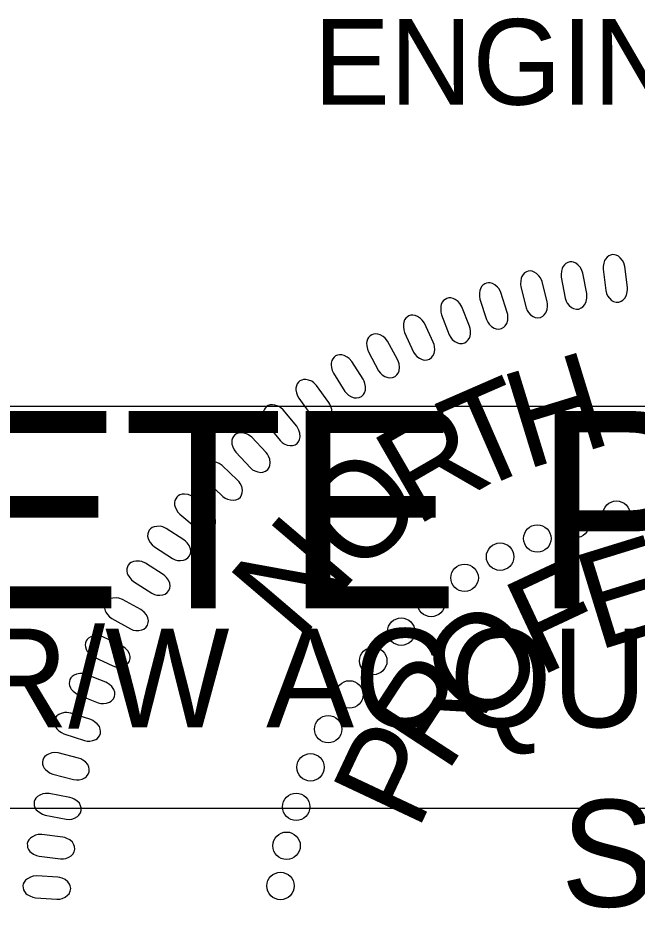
# Model space of a CAD drawing. Extents: x 505602 to 507286, y 483109 to 484209.
# Drawn here: x 507178.9 to 507215, y 484096.7 to 484148.7 of the extents above; entities that cross this region are included whole.
import ezdxf

# ---------------------------------------------------------------- set-up
doc = ezdxf.new("R2010")
doc.units = 0
for name, color, linetype in [('Sheet PE Seal Cell', 7, 'Continuous'), ('Sheet Profile CELL', 7, 'Continuous'), ('Sheet Sticker Incomplete CELL', 7, 'Continuous')]:
    doc.layers.add(name, color=color, linetype=linetype)

msp = doc.modelspace()

# ---------------------------------------------------------------- linework, layer by layer
at = {"layer": 'Sheet PE Seal Cell'}
for points in [[(507214.482, 484132.953), (507214.328, 484134.17), (507214.264, 484134.383), (507214.194, 484134.515), (507214.062, 484134.669), (507213.952, 484134.766), (507213.831, 484134.831), (507213.722, 484134.857), (507213.608, 484134.863), (507213.499, 484134.829), (507213.384, 484134.785), (507213.288, 484134.712), (507213.196, 484134.6), (507213.147, 484134.514), (507213.099, 484134.357), (507213.062, 484134.171), (507213.06, 484134.01), (507213.21, 484132.763), (507213.253, 484132.597), (507213.315, 484132.464), (507213.424, 484132.317), (507213.553, 484132.193), (507213.659, 484132.126), (507213.822, 484132.085), (507213.973, 484132.084), (507214.116, 484132.143), (507214.214, 484132.206), (507214.328, 484132.32), (507214.425, 484132.503), (507214.469, 484132.69), (507214.483, 484132.822)], [(507212.1, 484132.585), (507211.871, 484133.789), (507211.793, 484133.998), (507211.716, 484134.126), (507211.574, 484134.271), (507211.458, 484134.361), (507211.333, 484134.418), (507211.223, 484134.438), (507211.109, 484134.437), (507211.002, 484134.396), (507210.891, 484134.344), (507210.799, 484134.266), (507210.714, 484134.148), (507210.671, 484134.058), (507210.633, 484133.899), (507210.608, 484133.712), (507210.615, 484133.551), (507210.843, 484132.315), (507210.897, 484132.152), (507210.967, 484132.024), (507211.085, 484131.884), (507211.221, 484131.767), (507211.332, 484131.707), (507211.497, 484131.678), (507211.647, 484131.687), (507211.787, 484131.754), (507211.881, 484131.822), (507211.987, 484131.944), (507212.073, 484132.133), (507212.105, 484132.322), (507212.11, 484132.454)], [(507209.795, 484132.113), (507209.491, 484133.301), (507209.4, 484133.504), (507209.314, 484133.627), (507209.164, 484133.763), (507209.042, 484133.845), (507208.914, 484133.894), (507208.802, 484133.908), (507208.689, 484133.899), (507208.585, 484133.852), (507208.477, 484133.793), (507208.39, 484133.709), (507208.314, 484133.586), (507208.276, 484133.494), (507208.247, 484133.332), (507208.234, 484133.144), (507208.252, 484132.984), (507208.557, 484131.764), (507208.621, 484131.606), (507208.699, 484131.482), (507208.826, 484131.349), (507208.969, 484131.242), (507209.083, 484131.189), (507209.25, 484131.169), (507209.4, 484131.188), (507209.535, 484131.263), (507209.624, 484131.337), (507209.722, 484131.466), (507209.795, 484131.66), (507209.816, 484131.851), (507209.813, 484131.983)], [(507207.461, 484131.492), (507207.083, 484132.659), (507206.98, 484132.856), (507206.887, 484132.972), (507206.728, 484133.099), (507206.602, 484133.174), (507206.47, 484133.215), (507206.358, 484133.221), (507206.246, 484133.205), (507206.145, 484133.152), (507206.041, 484133.086), (507205.96, 484132.997), (507205.891, 484132.87), (507205.859, 484132.775), (507205.84, 484132.612), (507205.839, 484132.423), (507205.867, 484132.264), (507206.248, 484131.067), (507206.322, 484130.913), (507206.407, 484130.794), (507206.542, 484130.669), (507206.692, 484130.571), (507206.809, 484130.525), (507206.977, 484130.517), (507207.125, 484130.544), (507207.255, 484130.628), (507207.339, 484130.708), (507207.429, 484130.842), (507207.49, 484131.04), (507207.499, 484131.232), (507207.487, 484131.364)], [(507205.261, 484130.675), (507204.809, 484131.816), (507204.694, 484132.007), (507204.594, 484132.117), (507204.427, 484132.234), (507204.297, 484132.3), (507204.163, 484132.333), (507204.051, 484132.331), (507203.94, 484132.308), (507203.843, 484132.249), (507203.742, 484132.177), (507203.667, 484132.083), (507203.606, 484131.952), (507203.58, 484131.856), (507203.572, 484131.692), (507203.583, 484131.503), (507203.621, 484131.346), (507204.076, 484130.175), (507204.159, 484130.026), (507204.253, 484129.912), (507204.395, 484129.797), (507204.55, 484129.708), (507204.67, 484129.669), (507204.838, 484129.672), (507204.984, 484129.709), (507205.108, 484129.801), (507205.187, 484129.885), (507205.269, 484130.025), (507205.318, 484130.226), (507205.314, 484130.418), (507205.295, 484130.55)], [(507203.143, 484129.743), (507202.621, 484130.853), (507202.494, 484131.035), (507202.387, 484131.14), (507202.214, 484131.246), (507202.079, 484131.303), (507201.944, 484131.328), (507201.832, 484131.319), (507201.722, 484131.29), (507201.629, 484131.224), (507201.534, 484131.146), (507201.464, 484131.048), (507201.412, 484130.913), (507201.392, 484130.815), (507201.395, 484130.651), (507201.417, 484130.463), (507201.464, 484130.309), (507201.993, 484129.169), (507202.085, 484129.025), (507202.185, 484128.918), (507202.334, 484128.812), (507202.495, 484128.733), (507202.617, 484128.702), (507202.784, 484128.715), (507202.928, 484128.76), (507203.046, 484128.86), (507203.12, 484128.95), (507203.192, 484129.094), (507203.229, 484129.298), (507203.213, 484129.489), (507203.185, 484129.619)], [(507201.06, 484128.729), (507200.469, 484129.804), (507200.331, 484129.979), (507200.218, 484130.076), (507200.038, 484130.17), (507199.9, 484130.22), (507199.764, 484130.236), (507199.653, 484130.22), (507199.545, 484130.184), (507199.456, 484130.113), (507199.366, 484130.029), (507199.303, 484129.926), (507199.259, 484129.788), (507199.245, 484129.689), (507199.258, 484129.526), (507199.292, 484129.339), (507199.349, 484129.189), (507199.948, 484128.084), (507200.049, 484127.946), (507200.156, 484127.845), (507200.311, 484127.749), (507200.477, 484127.68), (507200.6, 484127.657), (507200.767, 484127.68), (507200.907, 484127.735), (507201.019, 484127.841), (507201.087, 484127.935), (507201.15, 484128.084), (507201.173, 484128.29), (507201.146, 484128.48), (507201.109, 484128.608)], [(507199.043, 484127.587), (507198.386, 484128.623), (507198.237, 484128.788), (507198.118, 484128.878), (507197.933, 484128.962), (507197.792, 484129.002), (507197.655, 484129.009), (507197.544, 484128.987), (507197.439, 484128.943), (507197.355, 484128.867), (507197.27, 484128.777), (507197.214, 484128.671), (507197.179, 484128.531), (507197.171, 484128.431), (507197.194, 484128.269), (507197.24, 484128.085), (507197.306, 484127.938), (507197.973, 484126.873), (507198.083, 484126.742), (507198.196, 484126.648), (507198.357, 484126.561), (507198.526, 484126.504), (507198.651, 484126.488), (507198.816, 484126.522), (507198.952, 484126.585), (507199.058, 484126.698), (507199.119, 484126.797), (507199.173, 484126.949), (507199.183, 484127.156), (507199.144, 484127.344), (507199.1, 484127.469)], [(507197.042, 484126.232), (507196.321, 484127.225), (507196.162, 484127.38), (507196.038, 484127.463), (507195.847, 484127.534), (507195.704, 484127.566), (507195.567, 484127.564), (507195.458, 484127.535), (507195.356, 484127.485), (507195.277, 484127.404), (507195.198, 484127.309), (507195.149, 484127.199), (507195.122, 484127.057), (507195.121, 484126.957), (507195.155, 484126.796), (507195.211, 484126.616), (507195.287, 484126.474), (507196.019, 484125.453), (507196.137, 484125.329), (507196.255, 484125.242), (507196.421, 484125.165), (507196.594, 484125.118), (507196.72, 484125.111), (507196.882, 484125.155), (507197.015, 484125.227), (507197.112, 484125.347), (507197.167, 484125.448), (507197.212, 484125.604), (507197.209, 484125.811), (507197.158, 484125.996), (507197.106, 484126.119)], [(507195.162, 484124.843), (507194.38, 484125.789), (507194.212, 484125.934), (507194.082, 484126.008), (507193.888, 484126.067), (507193.743, 484126.09), (507193.606, 484126.08), (507193.5, 484126.044), (507193.401, 484125.988), (507193.327, 484125.901), (507193.254, 484125.802), (507193.211, 484125.689), (507193.194, 484125.545), (507193.199, 484125.446), (507193.242, 484125.287), (507193.31, 484125.111), (507193.395, 484124.973), (507194.189, 484124.001), (507194.315, 484123.884), (507194.439, 484123.805), (507194.609, 484123.74), (507194.785, 484123.704), (507194.911, 484123.704), (507195.07, 484123.758), (507195.198, 484123.838), (507195.287, 484123.964), (507195.336, 484124.069), (507195.371, 484124.226), (507195.354, 484124.433), (507195.292, 484124.614), (507195.232, 484124.734)], [(507193.374, 484123.304), (507192.535, 484124.199), (507192.357, 484124.333), (507192.223, 484124.4), (507192.025, 484124.446), (507191.88, 484124.46), (507191.744, 484124.441), (507191.64, 484124.399), (507191.544, 484124.337), (507191.476, 484124.245), (507191.409, 484124.141), (507191.374, 484124.026), (507191.366, 484123.882), (507191.377, 484123.783), (507191.43, 484123.628), (507191.51, 484123.456), (507191.602, 484123.325), (507192.457, 484122.403), (507192.589, 484122.294), (507192.717, 484122.224), (507192.892, 484122.169), (507193.07, 484122.143), (507193.195, 484122.151), (507193.35, 484122.215), (507193.473, 484122.303), (507193.554, 484122.435), (507193.597, 484122.543), (507193.622, 484122.702), (507193.593, 484122.907), (507193.518, 484123.085), (507193.452, 484123.199)], [(507191.712, 484121.695), (507190.818, 484122.535), (507190.632, 484122.658), (507190.495, 484122.715), (507190.294, 484122.75), (507190.148, 484122.754), (507190.013, 484122.727), (507189.912, 484122.678), (507189.821, 484122.61), (507189.759, 484122.515), (507189.699, 484122.407), (507189.67, 484122.29), (507189.671, 484122.145), (507189.689, 484122.047), (507189.751, 484121.895), (507189.841, 484121.729), (507189.942, 484121.603), (507190.853, 484120.737), (507190.992, 484120.638), (507191.124, 484120.575), (507191.302, 484120.531), (507191.48, 484120.517), (507191.605, 484120.533), (507191.757, 484120.606), (507191.873, 484120.702), (507191.946, 484120.838), (507191.982, 484120.948), (507191.996, 484121.11), (507191.955, 484121.313), (507191.87, 484121.485), (507191.796, 484121.595)], [(507190.098, 484119.908), (507189.154, 484120.69), (507188.96, 484120.801), (507188.82, 484120.85), (507188.617, 484120.872), (507188.471, 484120.867), (507188.339, 484120.831), (507188.241, 484120.776), (507188.154, 484120.702), (507188.098, 484120.604), (507188.045, 484120.492), (507188.024, 484120.374), (507188.034, 484120.229), (507188.057, 484120.132), (507188.13, 484119.985), (507188.23, 484119.824), (507188.338, 484119.706), (507189.301, 484118.899), (507189.446, 484118.807), (507189.583, 484118.753), (507189.763, 484118.721), (507189.941, 484118.718), (507190.065, 484118.742), (507190.211, 484118.825), (507190.322, 484118.927), (507190.387, 484119.068), (507190.415, 484119.18), (507190.419, 484119.342), (507190.365, 484119.542), (507190.27, 484119.708), (507190.188, 484119.814)], [(507188.574, 484118.206), (507187.544, 484118.872), (507187.339, 484118.959), (507187.193, 484118.991), (507186.99, 484118.989), (507186.845, 484118.967), (507186.718, 484118.916), (507186.628, 484118.85), (507186.55, 484118.766), (507186.505, 484118.661), (507186.466, 484118.544), (507186.459, 484118.424), (507186.486, 484118.282), (507186.52, 484118.189), (507186.61, 484118.051), (507186.728, 484117.903), (507186.85, 484117.798), (507187.901, 484117.11), (507188.056, 484117.036), (507188.197, 484116.999), (507188.38, 484116.987), (507188.558, 484117.006), (507188.678, 484117.044), (507188.813, 484117.144), (507188.911, 484117.258), (507188.959, 484117.405), (507188.974, 484117.52), (507188.959, 484117.681), (507188.882, 484117.873), (507188.767, 484118.027), (507188.674, 484118.123)], [(507187.359, 484116.183), (507186.324, 484116.84), (507186.119, 484116.927), (507185.973, 484116.958), (507185.769, 484116.954), (507185.625, 484116.931), (507185.497, 484116.879), (507185.408, 484116.812), (507185.33, 484116.727), (507185.287, 484116.622), (507185.249, 484116.505), (507185.243, 484116.385), (507185.271, 484116.243), (507185.306, 484116.15), (507185.397, 484116.012), (507185.516, 484115.866), (507185.639, 484115.762), (507186.696, 484115.082), (507186.851, 484115.01), (507186.993, 484114.973), (507187.175, 484114.963), (507187.353, 484114.983), (507187.473, 484115.022), (507187.607, 484115.123), (507187.704, 484115.238), (507187.751, 484115.385), (507187.765, 484115.501), (507187.749, 484115.662), (507187.67, 484115.853), (507187.554, 484116.006), (507187.461, 484116.101)], [(507186.056, 484114.134), (507184.981, 484114.725), (507184.771, 484114.798), (507184.623, 484114.82), (507184.421, 484114.803), (507184.277, 484114.771), (507184.154, 484114.712), (507184.069, 484114.639), (507183.997, 484114.55), (507183.961, 484114.442), (507183.929, 484114.323), (507183.931, 484114.203), (507183.968, 484114.063), (507184.009, 484113.972), (507184.107, 484113.841), (507184.236, 484113.702), (507184.365, 484113.605), (507185.462, 484112.993), (507185.621, 484112.931), (507185.765, 484112.903), (507185.949, 484112.905), (507186.125, 484112.936), (507186.242, 484112.983), (507186.37, 484113.091), (507186.459, 484113.213), (507186.496, 484113.363), (507186.503, 484113.478), (507186.477, 484113.638), (507186.386, 484113.824), (507186.262, 484113.97), (507186.162, 484114.058)], [(507184.947, 484112.01), (507183.837, 484112.533), (507183.623, 484112.593), (507183.474, 484112.605), (507183.273, 484112.576), (507183.132, 484112.534), (507183.013, 484112.467), (507182.932, 484112.389), (507182.866, 484112.296), (507182.836, 484112.186), (507182.813, 484112.065), (507182.822, 484111.946), (507182.868, 484111.808), (507182.914, 484111.72), (507183.021, 484111.595), (507183.158, 484111.464), (507183.292, 484111.376), (507184.427, 484110.834), (507184.589, 484110.782), (507184.735, 484110.764), (507184.917, 484110.777), (507185.091, 484110.819), (507185.205, 484110.872), (507185.326, 484110.989), (507185.408, 484111.116), (507185.435, 484111.268), (507185.435, 484111.384), (507185.399, 484111.541), (507185.297, 484111.722), (507185.163, 484111.859), (507185.058, 484111.941)], [(507184.008, 484109.891), (507182.868, 484110.343), (507182.65, 484110.389), (507182.501, 484110.392), (507182.302, 484110.35), (507182.164, 484110.3), (507182.049, 484110.225), (507181.973, 484110.142), (507181.913, 484110.046), (507181.89, 484109.934), (507181.874, 484109.812), (507181.891, 484109.693), (507181.945, 484109.559), (507181.997, 484109.474), (507182.112, 484109.356), (507182.257, 484109.235), (507182.396, 484109.155), (507183.562, 484108.685), (507183.727, 484108.644), (507183.874, 484108.634), (507184.055, 484108.658), (507184.226, 484108.711), (507184.337, 484108.772), (507184.451, 484108.896), (507184.524, 484109.027), (507184.542, 484109.181), (507184.534, 484109.297), (507184.488, 484109.452), (507184.374, 484109.625), (507184.232, 484109.754), (507184.122, 484109.83)], [(507183.132, 484107.702), (507181.965, 484108.081), (507181.745, 484108.113), (507181.596, 484108.107), (507181.4, 484108.053), (507181.265, 484107.994), (507181.155, 484107.912), (507181.085, 484107.826), (507181.032, 484107.725), (507181.016, 484107.612), (507181.007, 484107.489), (507181.032, 484107.372), (507181.094, 484107.241), (507181.152, 484107.159), (507181.273, 484107.049), (507181.425, 484106.937), (507181.57, 484106.866), (507182.763, 484106.47), (507182.931, 484106.439), (507183.078, 484106.439), (507183.257, 484106.474), (507183.424, 484106.538), (507183.531, 484106.605), (507183.636, 484106.736), (507183.701, 484106.872), (507183.709, 484107.027), (507183.694, 484107.141), (507183.639, 484107.294), (507183.515, 484107.46), (507183.364, 484107.579), (507183.25, 484107.648)], [(507182.428, 484105.446), (507181.239, 484105.752), (507181.018, 484105.77), (507180.869, 484105.755), (507180.677, 484105.688), (507180.547, 484105.621), (507180.441, 484105.533), (507180.377, 484105.441), (507180.329, 484105.337), (507180.321, 484105.224), (507180.32, 484105.1), (507180.352, 484104.984), (507180.423, 484104.858), (507180.485, 484104.78), (507180.613, 484104.678), (507180.772, 484104.576), (507180.921, 484104.514), (507182.136, 484104.194), (507182.306, 484104.173), (507182.452, 484104.182), (507182.629, 484104.229), (507182.792, 484104.303), (507182.894, 484104.377), (507182.991, 484104.514), (507183.047, 484104.654), (507183.046, 484104.809), (507183.024, 484104.923), (507182.959, 484105.071), (507182.825, 484105.228), (507182.667, 484105.338), (507182.549, 484105.399)], [(507181.916, 484103.151), (507180.712, 484103.381), (507180.489, 484103.385), (507180.342, 484103.361), (507180.154, 484103.282), (507180.028, 484103.207), (507179.929, 484103.112), (507179.87, 484103.017), (507179.829, 484102.911), (507179.828, 484102.797), (507179.835, 484102.673), (507179.874, 484102.56), (507179.952, 484102.438), (507180.019, 484102.364), (507180.154, 484102.27), (507180.319, 484102.177), (507180.471, 484102.126), (507181.705, 484101.882), (507181.875, 484101.873), (507182.021, 484101.891), (507182.194, 484101.949), (507182.352, 484102.032), (507182.449, 484102.113), (507182.537, 484102.256), (507182.585, 484102.399), (507182.574, 484102.554), (507182.544, 484102.666), (507182.47, 484102.809), (507182.327, 484102.959), (507182.162, 484103.058), (507182.041, 484103.112)], [(507181.496, 484100.836), (507180.279, 484100.99), (507180.057, 484100.981), (507179.911, 484100.947), (507179.729, 484100.857), (507179.608, 484100.775), (507179.515, 484100.673), (507179.462, 484100.574), (507179.428, 484100.465), (507179.434, 484100.352), (507179.449, 484100.229), (507179.495, 484100.118), (507179.581, 484100.002), (507179.653, 484099.932), (507179.792, 484099.847), (507179.963, 484099.765), (507180.118, 484099.722), (507181.364, 484099.557), (507181.535, 484099.558), (507181.679, 484099.585), (507181.848, 484099.654), (507182.001, 484099.748), (507182.093, 484099.835), (507182.172, 484099.982), (507182.211, 484100.129), (507182.189, 484100.281), (507182.153, 484100.392), (507182.07, 484100.53), (507181.917, 484100.67), (507181.747, 484100.76), (507181.623, 484100.805)], [(507181.21, 484098.492), (507179.985, 484098.57), (507179.764, 484098.546), (507179.621, 484098.503), (507179.445, 484098.402), (507179.329, 484098.312), (507179.242, 484098.205), (507179.196, 484098.103), (507179.169, 484097.992), (507179.182, 484097.879), (507179.205, 484097.758), (507179.257, 484097.65), (507179.35, 484097.539), (507179.426, 484097.474), (507179.571, 484097.398), (507179.746, 484097.326), (507179.904, 484097.294), (507181.158, 484097.207), (507181.329, 484097.219), (507181.471, 484097.255), (507181.636, 484097.335), (507181.782, 484097.437), (507181.868, 484097.529), (507181.937, 484097.682), (507181.967, 484097.831), (507181.936, 484097.982), (507181.893, 484098.09), (507181.802, 484098.223), (507181.64, 484098.353), (507181.465, 484098.432), (507181.338, 484098.469)]]:
    msp.add_lwpolyline(points, close=True, dxfattribs=at)
for centre in [(507213.835, 484119.671), (507211.446, 484119.114), (507209.216, 484118.278), (507207.041, 484117.218), (507204.971, 484115.983), (507203.019, 484114.51), (507201.267, 484112.837), (507199.634, 484111.125), (507198.24, 484109.173), (507197.005, 484107.142), (507195.969, 484104.912), (507195.132, 484102.601), (507194.574, 484100.331), (507194.215, 484097.98)]:
    msp.add_circle(centre, 0.801, dxfattribs=at)
at = {"layer": 'Sheet Sticker Incomplete CELL'}
msp.add_lwpolyline([(507095.597, 484102.505), (507095.597, 484126.005), (507242.597, 484126.005), (507242.597, 484102.505)], close=True, dxfattribs=at)

# ---------------------------------------------------------------- texts
at = {"layer": 'Sheet PE Seal Cell'}
for s, height, rotation, p in [('H', 5.669, 17.0557, (507208.505, 484122.276)), ('T', 5.669, 23.5451, (507205.326, 484120.866)), ('R', 5.669, 30.0345, (507202.105, 484118.947)), ('O', 5.669, 43.0132, (507198.63, 484115.919)), ('N', 5.669, 49.5025, (507195.283, 484112.163)), ('E', 5.669, 17.1686, (507212.701, 484111.706)), ('F', 5.669, 25.1084, (507209.311, 484110.168)), ('O', 5.669, 40.988, (507205.614, 484107.029)), ('R', 5.669, 56.8676, (507203.9, 484104.483)), ('P', 5.669, 64.8074, (507202.214, 484101.121)), ('SEAL', 6.2363, 359.9814, (507210.585, 484096.772))]:
    msp.add_text(s, height=height, rotation=rotation, dxfattribs=at).set_placement(p)
at = {"layer": 'Sheet Profile CELL'}
msp.add_text('ENGINEER', height=5.0001, dxfattribs=at).set_placement((507196.142, 484143.624))
at = {"layer": 'Sheet Sticker Incomplete CELL'}
for s, height, p in [('INCOMPLETE PLANS', 11.52, (507104.547, 484114.205)), ('DO NOT USE FOR R/W ACQUISITION', 5.76, (507107.797, 484107.255))]:
    msp.add_text(s, height=height, dxfattribs=at).set_placement(p)

doc.saveas('drawing.dxf')
